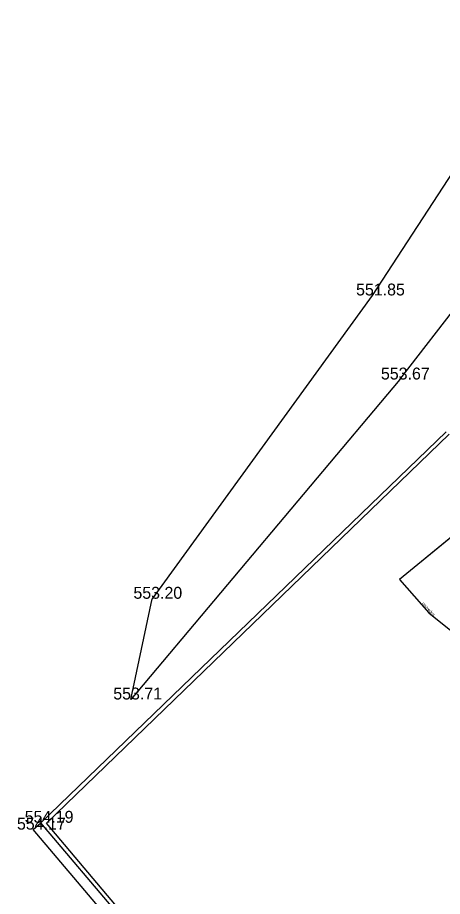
# Model space of a CAD drawing. Extents: x -669995 to -669686, y -1125551 to -1125263.
# Drawn here: x -669967.7 to -669941, y -1125457 to -1125401.7 of the extents above; entities that cross this region are included whole.
import ezdxf

# ---------------------------------------------------------------- set-up
doc = ezdxf.new("R2010")
doc.units = 0
for name, color, linetype in [('G_Bod_tecka', 7, 'Continuous'), ('G_Bod_vyska', 7, 'Continuous'), ('G_Breh_Teren', 7, 'Continuous'), ('G_Plochy_zpevnene', 7, 'Continuous'), ('G_Ploty', 7, 'Continuous'), ('G_Z_KANAL_podz_kotovane', 7, 'Continuous'), ('Vrstva 13', 7, 'Continuous'), ('Vrstva 3', 7, 'Continuous')]:
    doc.layers.add(name, color=color, linetype=linetype)

msp = doc.modelspace()

# ---------------------------------------------------------------- linework, layer by layer
at = {"layer": 'G_Bod_tecka'}
for p, q in [((-669945.39, -1125419.19), (-669945.39, -1125419.19)), ((-669943.66, -1125424.48), (-669943.66, -1125424.48)), ((-669959.22, -1125438.28), (-669959.22, -1125438.28)), ((-669960.57, -1125444.62), (-669960.57, -1125444.62)), ((-669966.22, -1125452.38), (-669966.22, -1125452.38)), ((-669966.71, -1125452.81), (-669966.71, -1125452.81))]:
    msp.add_line(p, q, dxfattribs=at)
at = {"layer": 'G_Breh_Teren'}
for p, q in [((-669918.8, -1125378.37), (-669945.39, -1125419.19)), ((-669943.66, -1125424.48), (-669910.9, -1125382.13))]:
    msp.add_line(p, q, dxfattribs=at)
for points in [[(-669945.39, -1125419.19), (-669959.22, -1125438.28)], [(-669943.66, -1125424.48), (-669960.57, -1125444.62)], [(-669960.57, -1125444.62), (-669959.22, -1125438.28)]]:
    msp.add_lwpolyline(points, dxfattribs=at)
at = {"layer": 'G_Plochy_zpevnene'}
for points in [[(-669966.71, -1125452.81), (-669966.22, -1125452.38)], [(-669938.39, -1125486.26), (-669966.71, -1125452.81)]]:
    msp.add_lwpolyline(points, dxfattribs=at)
at = {"layer": 'G_Ploty'}
for p, q in [((-669940.74, -1125427.77), (-669966.22, -1125452.38)), ((-669965.88, -1125452.4), (-669940.55, -1125427.93)), ((-669937.94, -1125485.86), (-669966.22, -1125452.38)), ((-669937.91, -1125485.51), (-669965.88, -1125452.4))]:
    msp.add_line(p, q, dxfattribs=at)
at = {"layer": 'G_Z_KANAL_podz_kotovane'}
msp.add_lwpolyline([(-669928.74, -1125427.81), (-669930.24, -1125426.07), (-669943.68, -1125437.06), (-669941.82, -1125439.16), (-669920.27, -1125456.43), (-669898.38, -1125455.52)], dxfattribs=at)
at = {"layer": 'Vrstva 13'}
msp.add_lwpolyline([(-669928.742, -1125427.808), (-669930.244, -1125426.067), (-669943.68, -1125437.06), (-669941.82, -1125439.16), (-669920.27, -1125456.43), (-669898.384, -1125455.525)], dxfattribs=at)

# ---------------------------------------------------------------- texts
at = {"layer": 'G_Bod_vyska'}
for s, p in [('551.85', (-669946.402, -1125419.19)), ('553.67', (-669944.838, -1125424.48)), ('553.20', (-669960.406, -1125438.28)), ('553.71', (-669961.672, -1125444.62)), ('554.19', (-669967.244, -1125452.38)), ('554.17', (-669967.732, -1125452.81))]:
    msp.add_text(s, height=0.75, dxfattribs=at).set_placement(p)
at = {"layer": 'Vrstva 3'}
msp.add_text('neuveden', height=0.1755, rotation=311.5606, dxfattribs=at).set_placement((-669942.261, -1125438.583))

doc.saveas('drawing.dxf')
